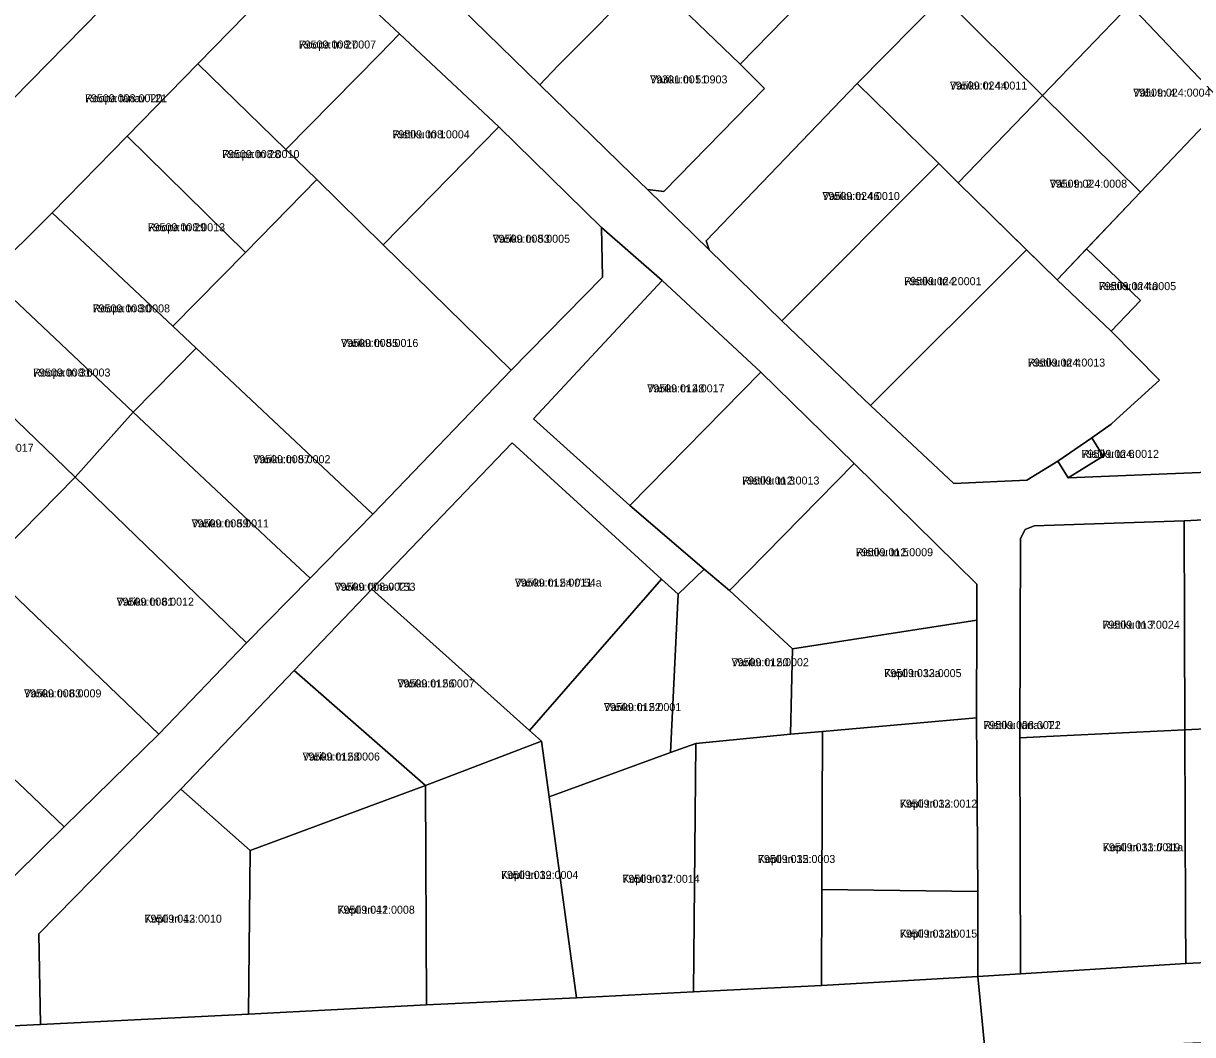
# Model space of a CAD drawing. Extents: x 643847 to 663718, y 6468443 to 6482775.
# Drawn here: x 658079.1 to 658298.3, y 6470744 to 6470933.7 of the extents above; entities that cross this region are included whole.
import ezdxf

# ---------------------------------------------------------------- set-up
doc = ezdxf.new("R2010")
doc.units = 0
for name, color, linetype in [('L_AADRESS', 7, 'Continuous'), ('PIIR', 7, 'Continuous'), ('TUNNUS', 7, 'Continuous')]:
    doc.layers.add(name, color=color, linetype=linetype)

msp = doc.modelspace()

# ---------------------------------------------------------------- linework, layer by layer
at = {"layer": 'PIIR'}
for points in [[(658235.32, 6471080.84), (658070.5, 6470912.78), (657931.36, 6470770.92), (657920.21, 6470763.4), (657894.79, 6470735.17), (657885.81, 6470724.45), (657740.37, 6470576), (657713.3, 6470606.52), (657725.26, 6470618.75), (657844.94, 6470741.13), (657950.03, 6470848.17), (657953.72, 6470844.8), (658007.99, 6470900.13), (658096.06, 6470989.93)], [(658322.62, 6470841.71), (658296.71, 6470840.35), (658268.61, 6470839.44), (658266.96, 6470838.73), (658266.04, 6470837.09), (658265.95, 6470799.69), (658266.03, 6470755.39), (658258.07, 6470754.9), (658258.05, 6470770.82), (658257.8, 6470803.42), (658257.84, 6470821.74), (658257.85, 6470828.47), (658234.85, 6470851.11), (658217.39, 6470868.3), (658198.9, 6470885.44), (658187.5, 6470895.4), (658168.26, 6470914.28), (658149.65, 6470931.73), (658132.78, 6470947.54)], [(658158.59, 6470939.16), (658175.92, 6470922.2), (658193.18, 6470905.38), (658196.11, 6470902.54), (658207.69, 6470891.23), (658221.34, 6470877.88), (658237.95, 6470862), (658253.53, 6470847.4), (658267.27, 6470848.01), (658273.03, 6470851.57), (658274.97, 6470848.44), (658302.87, 6470849.56)], [(658308.52, 6470742.77), (658291.63, 6470742.12), (658259.5, 6470740.08), (658258.07, 6470754.9), (658266.03, 6470755.39), (658297.04, 6470757.31), (658323.04, 6470758.58)], [(658068.14, 6470745.21), (658082.32, 6470745.9), (658121.29, 6470747.84), (658154.71, 6470749.61), (658182.82, 6470750.91), (658204.76, 6470752), (658228.77, 6470753.19), (658258.07, 6470754.9), (658259.5, 6470740.08), (658227.22, 6470738.46), (658202.98, 6470737.11), (658180.85, 6470736.03), (658161.36, 6470735.01), (658141.69, 6470733.99), (658113.88, 6470732.71), (658082.77, 6470731.18), (658068.79, 6470731.62)]]:
    msp.add_lwpolyline(points, dxfattribs=at)
for points in [[(658222.87, 6471039.8), (658210.49, 6471026.82), (658197.91, 6471013.99), (658185.36, 6471001.17), (658172.74, 6470988.35), (658161.52, 6470976.91), (658141.21, 6470956.22), (658132.78, 6470947.54), (658111.83, 6470926.13), (658098.56, 6470912.55), (658084.48, 6470898.16), (658072.55, 6470886.34), (658061.24, 6470875.13), (658044.3, 6470858.01), (658027.02, 6470840.2), (658002.46, 6470814.88), (657989.82, 6470801.86), (657986.99, 6470798.94), (657946.37, 6470757.08), (657931.36, 6470770.92), (658070.5, 6470912.78), (658235.32, 6471080.84), (658249.97, 6471066.62), (658242.3, 6471059.55)], [(658274.9, 6470988.81), (658295.37, 6471009.64), (658305.25, 6470994.12), (658292.03, 6470980.48), (658282.9, 6470971.04), (658267.02, 6470953.72), (658251.5, 6470938.76), (658235.43, 6470922.42), (658207.1, 6470892.92), (658207.69, 6470891.23), (658196.11, 6470902.54), (658199.2, 6470902.14), (658218.03, 6470921.48), (658213.47, 6470926.03), (658224.62, 6470937.44), (658247.56, 6470960.82), (658262.65, 6470976.32)], [(658301.14, 6470898.98), (658300.83, 6470886.85), (658302.87, 6470849.56), (658274.97, 6470848.44), (658281.56, 6470852.48), (658279.42, 6470855.93), (658283.05, 6470858.51), (658284.02, 6470859.4), (658292.11, 6470866.77), (658283.05, 6470875.94), (658288.56, 6470881.74), (658278.41, 6470891.38), (658288.56, 6470902.06), (658304.21, 6470918.53), (658317.01, 6470931.99), (658319.23, 6470937.89), (658323.28, 6470950.37), (658330.03, 6470971.14), (658335.89, 6470965.66), (658324.27, 6470932.56), (658328.66, 6470928.48), (658314.34, 6470913.12)], [(658213.47, 6470926.03), (658196.18, 6470942.74), (658187.47, 6470951.49), (658198.68, 6470962.9), (658224.62, 6470937.44)], [(658158.59, 6470939.16), (658162.09, 6470942.73), (658178.9, 6470959.87), (658187.47, 6470951.49), (658196.18, 6470942.74), (658179.4, 6470925.77), (658175.92, 6470922.2)], [(658267.02, 6470953.72), (658286.56, 6470937.16), (658270.16, 6470920.17), (658251.5, 6470938.76)], [(658317.01, 6470931.99), (658304.21, 6470918.53), (658286.56, 6470937.16), (658302.17, 6470953.31), (658319.23, 6470937.89)], [(658132.78, 6470947.54), (658149.65, 6470931.73), (658145.85, 6470927.87), (658128.32, 6470910.07), (658111.83, 6470926.13)], [(658179.4, 6470925.77), (658196.18, 6470942.74), (658213.47, 6470926.03), (658218.03, 6470921.48), (658199.2, 6470902.14), (658196.11, 6470902.54), (658193.18, 6470905.38), (658175.92, 6470922.2)], [(658251.5, 6470938.76), (658270.16, 6470920.17), (658254.36, 6470903.82), (658250.74, 6470907.41), (658235.43, 6470922.42)], [(658270.16, 6470920.17), (658286.56, 6470937.16), (658304.21, 6470918.53), (658288.56, 6470902.06)], [(658168.26, 6470914.28), (658146.55, 6470892.16), (658134.15, 6470904.39), (658128.32, 6470910.07), (658145.85, 6470927.87), (658149.65, 6470931.73)], [(658111.83, 6470926.13), (658128.32, 6470910.07), (658134.15, 6470904.39), (658120.73, 6470890.74), (658098.56, 6470912.55)], [(658235.43, 6470922.42), (658250.74, 6470907.41), (658221.34, 6470877.88), (658207.69, 6470891.23), (658207.1, 6470892.92)], [(658270.16, 6470920.17), (658288.56, 6470902.06), (658272.9, 6470885.58), (658254.36, 6470903.82)], [(658187.5, 6470895.4), (658187.66, 6470886.08), (658170.54, 6470868.63), (658146.55, 6470892.16), (658168.26, 6470914.28)], [(658098.56, 6470912.55), (658120.73, 6470890.74), (658107.12, 6470876.87), (658084.48, 6470898.16)], [(658221.34, 6470877.88), (658250.74, 6470907.41), (658254.36, 6470903.82), (658267.15, 6470891.24), (658237.95, 6470862)], [(658144.63, 6470841.6), (658137.35, 6470848.45), (658111.49, 6470872.76), (658107.12, 6470876.87), (658120.73, 6470890.74), (658134.15, 6470904.39), (658146.55, 6470892.16), (658170.54, 6470868.63)], [(658084.48, 6470898.16), (658107.12, 6470876.87), (658111.49, 6470872.76), (658099.71, 6470860.79), (658072.55, 6470886.34)], [(658170.54, 6470868.63), (658187.66, 6470886.08), (658187.5, 6470895.4), (658198.9, 6470885.44), (658174.76, 6470859.49), (658192.84, 6470843.25), (658206.78, 6470831.33), (658201.89, 6470826.61), (658198.77, 6470829.43), (658170.73, 6470855.03), (658144.45, 6470827.53), (658129.88, 6470812.29), (658108.63, 6470790.05), (658082.01, 6470762.87), (658082.32, 6470745.9), (658068.14, 6470745.21), (658068.51, 6470765), (658086.79, 6470782.98), (658104.49, 6470800.37), (658120.97, 6470817.52), (658132.86, 6470829.62), (658144.63, 6470841.6)], [(658267.27, 6470848.01), (658253.53, 6470847.4), (658237.95, 6470862), (658267.15, 6470891.24), (658272.9, 6470885.58), (658283.05, 6470875.94), (658292.11, 6470866.77), (658284.02, 6470859.4), (658283.05, 6470858.51), (658279.42, 6470855.93), (658273.03, 6470851.57)], [(658272.9, 6470885.58), (658278.41, 6470891.38), (658288.56, 6470881.74), (658283.05, 6470875.94)], [(658072.55, 6470886.34), (658099.71, 6470860.79), (658088.85, 6470848.55), (658061.24, 6470875.13)], [(658174.76, 6470859.49), (658198.9, 6470885.44), (658217.39, 6470868.3), (658192.84, 6470843.25)], [(658044.3, 6470858.01), (658061.24, 6470875.13), (658088.85, 6470848.55), (658072.03, 6470831.53)], [(658132.86, 6470829.62), (658125.57, 6470836.47), (658099.71, 6470860.79), (658111.49, 6470872.76), (658137.35, 6470848.45), (658144.63, 6470841.6)], [(658234.85, 6470851.11), (658211.49, 6470827.29), (658206.78, 6470831.33), (658192.84, 6470843.25), (658217.39, 6470868.3)], [(658125.57, 6470836.47), (658132.86, 6470829.62), (658120.97, 6470817.52), (658088.85, 6470848.55), (658099.71, 6470860.79)], [(658274.97, 6470848.44), (658273.03, 6470851.57), (658279.42, 6470855.93), (658281.56, 6470852.48)], [(658170.73, 6470855.03), (658198.77, 6470829.43), (658174.01, 6470801.06), (658144.45, 6470827.53)], [(658257.85, 6470828.47), (658257.84, 6470821.74), (658223.3, 6470816.38), (658211.49, 6470827.29), (658234.85, 6470851.11)], [(658104.49, 6470800.37), (658072.03, 6470831.53), (658088.85, 6470848.55), (658120.97, 6470817.52)], [(658266.96, 6470838.73), (658268.61, 6470839.44), (658296.71, 6470840.35), (658296.86, 6470801.17), (658270.94, 6470799.93), (658265.95, 6470799.69), (658266.04, 6470837.09)], [(658296.71, 6470840.35), (658322.62, 6470841.71), (658322.83, 6470802.42), (658296.86, 6470801.17)], [(658086.79, 6470782.98), (658079.42, 6470789.96), (658054.29, 6470813.76), (658072.03, 6470831.53), (658104.49, 6470800.37)], [(658201.89, 6470826.61), (658200.46, 6470796.91), (658177.67, 6470788.59), (658176.24, 6470799.06), (658174.01, 6470801.06), (658198.77, 6470829.43)], [(658206.78, 6470831.33), (658211.49, 6470827.29), (658223.3, 6470816.38), (658222.96, 6470800.38), (658205.16, 6470798.62), (658200.46, 6470796.91), (658201.89, 6470826.61)], [(658144.45, 6470827.53), (658174.01, 6470801.06), (658176.24, 6470799.06), (658154.51, 6470790.73), (658129.88, 6470812.29)], [(658257.84, 6470821.74), (658257.8, 6470803.42), (658228.91, 6470800.86), (658222.96, 6470800.38), (658223.3, 6470816.38)], [(658068.51, 6470765), (658045.66, 6470787.32), (658037.45, 6470795.35), (658054.29, 6470813.76), (658079.42, 6470789.96), (658086.79, 6470782.98)], [(658129.88, 6470812.29), (658154.51, 6470790.73), (658121.64, 6470778.54), (658108.63, 6470790.05)], [(658258.05, 6470770.82), (658228.82, 6470771.19), (658228.91, 6470800.86), (658257.8, 6470803.42)], [(658204.76, 6470752), (658205.16, 6470798.62), (658222.96, 6470800.38), (658228.91, 6470800.86), (658228.82, 6470771.19), (658228.77, 6470753.19)], [(658266.03, 6470755.39), (658265.95, 6470799.69), (658270.94, 6470799.93), (658296.86, 6470801.17), (658297.01, 6470766.67), (658297.04, 6470757.31)], [(658297.04, 6470757.31), (658297.01, 6470766.67), (658296.86, 6470801.17), (658322.83, 6470802.42), (658323.04, 6470758.58)], [(658154.71, 6470749.61), (658154.51, 6470790.73), (658176.24, 6470799.06), (658177.67, 6470788.59), (658182.82, 6470750.91)], [(658182.82, 6470750.91), (658177.67, 6470788.59), (658200.46, 6470796.91), (658205.16, 6470798.62), (658204.76, 6470752)], [(658082.32, 6470745.9), (658082.01, 6470762.87), (658108.63, 6470790.05), (658121.64, 6470778.54), (658121.29, 6470747.84)], [(658121.29, 6470747.84), (658121.64, 6470778.54), (658154.51, 6470790.73), (658154.71, 6470749.61)], [(658258.07, 6470754.9), (658228.77, 6470753.19), (658228.82, 6470771.19), (658258.05, 6470770.82)]]:
    msp.add_lwpolyline(points, close=True, dxfattribs=at)

# ---------------------------------------------------------------- texts
at = {"layer": 'L_AADRESS'}
for s, p in [('Roopa tn 27', (658130.74, 6470928.99)), ('Variku tn 51', (658196.61, 6470922.44)), ('Variku tn 44', (658252.81, 6470921.29)), ('Välu tn 4', (658287.18, 6470919.96)), ('Roopa tänav T21', (658090.66, 6470918.91)), ('Ristiku tn 1', (658148.29, 6470912.14)), ('Roopa tn 28', (658116.37, 6470908.43)), ('Välu tn 2', (658271.53, 6470902.88)), ('Variku tn 46', (658228.92, 6470900.57)), ('Roopa tn 29', (658102.42, 6470894.71)), ('Variku tn 53', (658167.1, 6470892.55)), ('Ristiku tn 2', (658244.25, 6470884.59)), ('Ristiku tn 4a', (658280.73, 6470883.66)), ('Roopa tn 30', (658092.1, 6470879.48)), ('Variku tn 55', (658138.66, 6470873)), ('Roopa tn 31', (658080.93, 6470867.45)), ('Ristiku tn 4', (658267.43, 6470869.32)), ('Variku tn 48', (658196.07, 6470864.48)), ('Ristiku tn 6', (658277.51, 6470852.19)), ('Variku tn 57', (658122.18, 6470851.19)), ('Ristiku tn 3', (658213.85, 6470847.19)), ('Variku tn 59', (658110.65, 6470839.15)), ('Ristiku tn 5', (658235.16, 6470833.74)), ('Variku tn 54 // 54a', (658171.25, 6470828.04)), ('Variku tänav T53', (658137.46, 6470827.26)), ('Variku tn 61', (658096.59, 6470824.46)), ('Ristiku tn 7', (658281.41, 6470820.14)), ('Variku tn 50', (658211.88, 6470813.11)), ('Kopli tn 33a', (658240.5, 6470811.06)), ('Variku tn 56', (658149.24, 6470809.13)), ('Variku tn 63', (658079.24, 6470807.26)), ('Variku tn 52', (658187.95, 6470804.69)), ('Ristiku tänav T1', (658259.1, 6470801.31)), ('Variku tn 58', (658131.46, 6470795.41)), ('Kopli tn 33', (658243.43, 6470786.58)), ('Kopli tn 31 // 31a', (658281.5, 6470778.39)), ('Kopli tn 35', (658216.83, 6470776.19)), ('Kopli tn 39', (658168.66, 6470773.21)), ('Kopli tn 37', (658191.41, 6470772.47)), ('Kopli tn 41', (658138, 6470766.67)), ('Kopli tn 43', (658101.82, 6470764.99)), ('Kopli tn 33b', (658243.43, 6470762.19))]:
    msp.add_text(s, height=1.5, dxfattribs=at).set_placement(p)
at = {"layer": 'TUNNUS'}
for s, p in [('79509:008:0007', (658130.74, 6470928.99)), ('79301:001:0903', (658196.61, 6470922.44)), ('79509:024:0011', (658252.81, 6470921.29)), ('79509:024:0004', (658287.18, 6470919.96)), ('79509:008:0020', (658090.66, 6470918.91)), ('79509:008:0004', (658148.29, 6470912.14)), ('79509:008:0010', (658116.37, 6470908.43)), ('79509:024:0008', (658271.53, 6470902.88)), ('79509:024:0010', (658228.92, 6470900.57)), ('79509:008:0013', (658102.42, 6470894.71)), ('79509:008:0005', (658167.1, 6470892.55)), ('79509:024:0001', (658244.25, 6470884.59)), ('79509:024:0005', (658280.73, 6470883.66)), ('79509:008:0008', (658092.1, 6470879.48)), ('79509:008:0016', (658138.66, 6470873)), ('79509:008:0003', (658080.93, 6470867.45)), ('79509:024:0013', (658267.43, 6470869.32)), ('79509:012:0017', (658196.07, 6470864.48)), ('79509:008:0017', (658066.54, 6470853.33)), ('79509:024:0012', (658277.51, 6470852.19)), ('79509:008:0002', (658122.18, 6470851.19)), ('79509:012:0013', (658213.85, 6470847.19)), ('79509:008:0011', (658110.65, 6470839.15)), ('79509:012:0009', (658235.16, 6470833.74)), ('79509:012:0011', (658171.25, 6470828.04)), ('79509:008:0021', (658137.46, 6470827.26)), ('79509:008:0012', (658096.59, 6470824.46)), ('79509:013:0024', (658281.41, 6470820.14)), ('79509:012:0002', (658211.88, 6470813.11)), ('79509:012:0005', (658240.5, 6470811.06)), ('79509:012:0007', (658149.24, 6470809.13)), ('79509:008:0009', (658079.24, 6470807.26)), ('79509:012:0001', (658187.95, 6470804.69)), ('79509:008:0022', (658259.1, 6470801.31)), ('79509:012:0006', (658131.46, 6470795.41)), ('79509:012:0012', (658243.43, 6470786.58)), ('79509:013:0019', (658281.5, 6470778.39)), ('79509:012:0003', (658216.83, 6470776.19)), ('79509:012:0004', (658168.66, 6470773.21)), ('79509:012:0014', (658191.41, 6470772.47)), ('79509:012:0008', (658138, 6470766.67)), ('79509:012:0010', (658101.82, 6470764.99)), ('79509:012:0015', (658243.43, 6470762.19))]:
    msp.add_text(s, height=1.5, dxfattribs=at).set_placement(p)

doc.saveas('drawing.dxf')
